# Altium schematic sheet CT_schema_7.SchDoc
size 274 x 160 mm
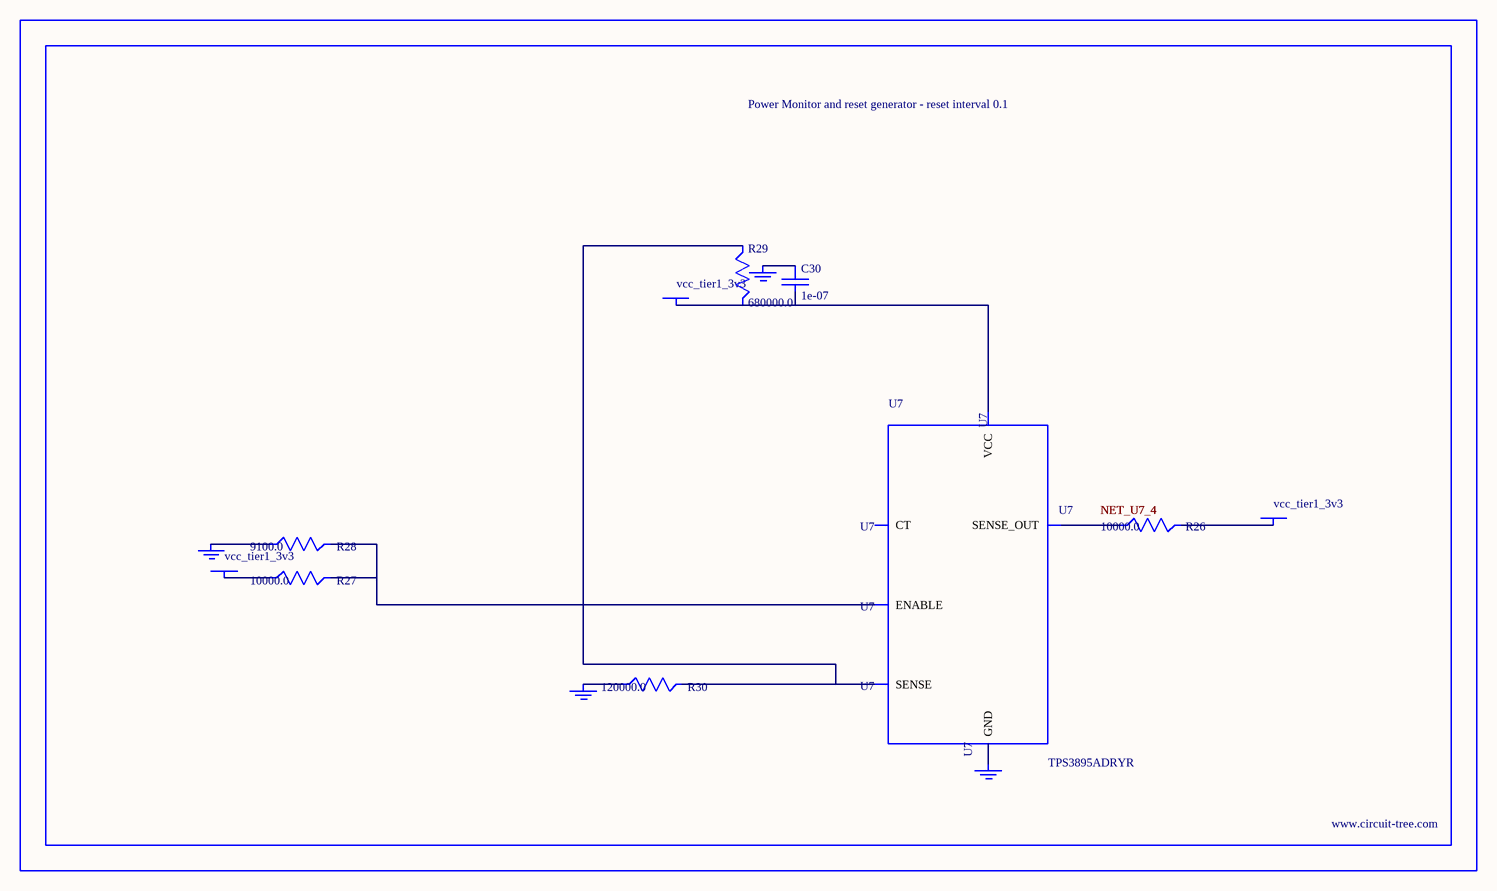
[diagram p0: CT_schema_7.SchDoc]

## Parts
BORDER6  (no value)
C30  1e-07  [C0402]
GND_INSTANCE_6_0  (no value)
GND_INSTANCE_6_1  (no value)
GND_INSTANCE_6_2  (no value)
GND_INSTANCE_6_3  (no value)
POWER_INSTANCE_6_0  vcc_tier1_3v3
POWER_INSTANCE_6_1  vcc_tier1_3v3
POWER_INSTANCE_6_2  vcc_tier1_3v3
R26  10000.0  [R0603]
R27  10000.0  [R0603]
R28  9100.0  [R0603]
R29  680000.0  [R0603]
R30  120000.0  [R0603]
U7  TPS3895ADRYR  [SON-6]

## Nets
NetC30_1: C30.1 GND_INSTANCE_6_2.0(GND)
NetC30_2: C30.2 POWER_INSTANCE_6_2.0(PWR) R29.2 U7.6(VCC)
NetGND_INSTANCE_6_0_0: GND_INSTANCE_6_0.0(GND) R28.1
NetGND_INSTANCE_6_1_0: GND_INSTANCE_6_1.0(GND) R30.1
NetGND_INSTANCE_6_3_0: GND_INSTANCE_6_3.0(GND) U7.2(GND)
NetPOWER_INSTANCE_6_0_0: POWER_INSTANCE_6_0.0(PWR) R27.1
NetPOWER_INSTANCE_6_1_0: POWER_INSTANCE_6_1.0(PWR) R26.2
NetR26_1: R26.1 U7.4(SENSE_OUT)
NetR27_2: R27.2 R28.2 U7.1(ENABLE)
NetR29_1: R29.1 R30.2 U7.3(SENSE)

Not connected (* = marked no-connect by the designer): U7 5(CT)

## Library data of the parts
BORDER6 = BORDER_PAGE6
C30 = C0402C104K3RACTU
GND_INSTANCE_6_0-GND_INSTANCE_6_3 = GND
POWER_INSTANCE_6_0-POWER_INSTANCE_6_2 = PWR
R26 R27 = RC0603JR-0710KL
R28 = RC0603JR-079K1L
R29 = RC0603JR-07680KL
R30 = RC0603JR-07120KL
